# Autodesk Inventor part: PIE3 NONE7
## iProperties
Shininess: 64.0
Length Units: 11269
Angle Units: 11279
Time Units: 11290
Mass Units: 11286
Length Display Precision: 3
Angle Display Precision: 2
Compacted: True
Part Number: PIE3 NONE7
Document SubType Name: Modeling
Created: 2004-08
Designer: John Blackburn
Manufacturer: Standard
Standards Organization: Custom
Density: 0.0
Volumn: 0.0
Area: 0.0
PropertySet Name: Model Information
Control State: 0
Master: False
Checked Out: False
Author: John Blackburn
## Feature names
1. Erst1
